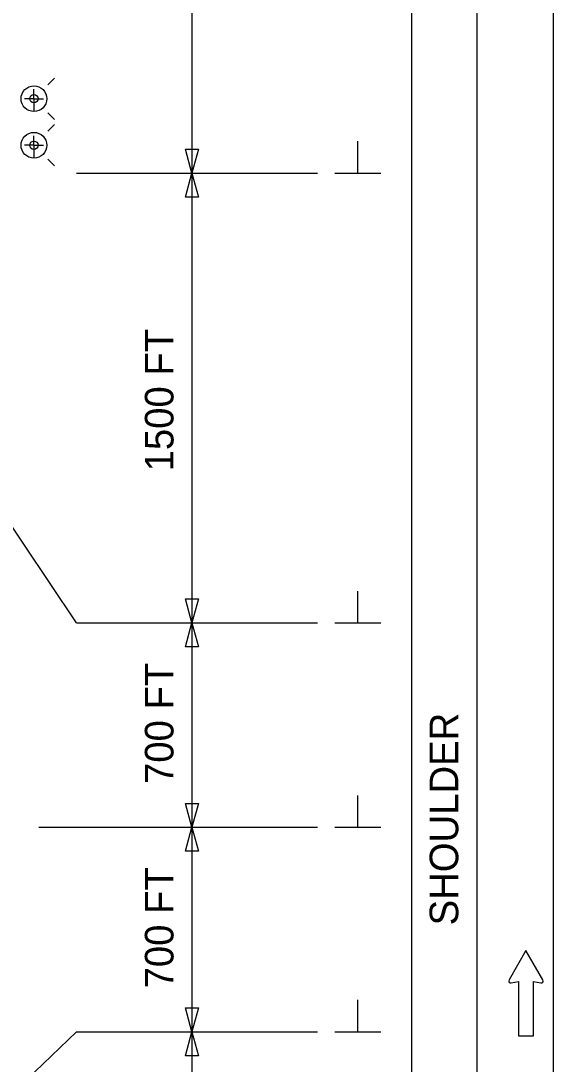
# Model space of a CAD drawing. Extents: x 15273 to 18137, y 1908 to 6555.
# Drawn here: x 16480.8 to 16611, y 2540.6 to 2795.7 of the extents above; entities that cross this region are included whole.
import ezdxf

# ---------------------------------------------------------------- set-up
doc = ezdxf.new("R2010")
doc.units = 0
for name, color, linetype in [('ALI_LEGAL_EX', 7, 'Continuous'), ('MT_SCRATCH_LEVEL_E', 7, 'Continuous'), ('PAVT_EDGE_EX', 7, 'Continuous'), ('TRAFFIC_SIGNS_PR', 7, 'Continuous'), ('TYPICAL_TEXT_DIMEN_PR', 7, 'Continuous')]:
    doc.layers.add(name, color=color, linetype=linetype)

msp = doc.modelspace()

# ---------------------------------------------------------------- linework, layer by layer
at = {"layer": 'ALI_LEGAL_EX'}
msp.add_line((16610.98, 3236.46), (16610.98, 2407.28), dxfattribs=at)
at = {"layer": 'MT_SCRATCH_LEVEL_E'}
for p, q in [((16604.32, 2568.38), (16600.21, 2561.14)), ((16608.47, 2561.14), (16604.32, 2568.38)), ((16600.69, 2560.45), (16602.47, 2560.77)), ((16602.47, 2560.77), (16602.47, 2547.51)), ((16606.21, 2547.51), (16606.21, 2560.77)), ((16606.21, 2560.77), (16607.99, 2560.45)), ((16602.47, 2547.51), (16606.21, 2547.51))]:
    msp.add_line(p, q, dxfattribs=at)
for centre, start, end in [((16600.62, 2560.91), 150.4248, 279.9638), ((16608.06, 2560.91), 260.0362, 29.7731)]:
    msp.add_arc(centre, 0.463, start, end, dxfattribs=at)
at = {"layer": 'PAVT_EDGE_EX'}
for p, q in [((16576.35, 3138.78), (16576.35, 2305.55)), ((16592.35, 3138.78), (16592.35, 2305.55))]:
    msp.add_line(p, q, dxfattribs=at)
at = {"layer": 'TRAFFIC_SIGNS_PR'}
for p, q in [((16487.39, 2780.1), (16489.02, 2781.72)), ((16483.96, 2776.67), (16483.96, 2778.97)), ((16483.96, 2776.67), (16481.66, 2776.67)), ((16483.96, 2776.67), (16483.96, 2773.52)), ((16483.96, 2776.67), (16486.27, 2776.67)), ((16489.01, 2771.62), (16487.39, 2773.25)), ((16487.39, 2768.7), (16489.02, 2770.33)), ((16483.96, 2765.28), (16483.96, 2767.58)), ((16483.96, 2765.28), (16481.66, 2765.28)), ((16483.96, 2765.28), (16483.96, 2762.13)), ((16483.96, 2765.28), (16486.27, 2765.28)), ((16489.01, 2760.23), (16487.39, 2761.86))]:
    msp.add_line(p, q, dxfattribs=at)
for centre, radius in [((16483.96, 2776.67), 3.15), ((16483.96, 2776.67), 1.02), ((16483.96, 2765.28), 3.15), ((16483.96, 2765.28), 1.02)]:
    msp.add_circle(centre, radius, dxfattribs=at)
at = {"layer": 'TYPICAL_TEXT_DIMEN_PR'}
for p, q in [((16522.62, 2868.48), (16522.62, 2758.48)), ((16563.23, 2758.48), (16563.23, 2766.26)), ((16522.62, 2758.48), (16521.06, 2764.34)), ((16521.06, 2764.34), (16522.62, 2764.34)), ((16522.62, 2764.34), (16524.19, 2764.34)), ((16524.19, 2764.34), (16522.62, 2758.48)), ((16494.38, 2758.48), (16553.35, 2758.48)), ((16521.06, 2752.61), (16522.62, 2758.48)), ((16521.06, 2752.61), (16522.62, 2758.48)), ((16522.62, 2758.48), (16522.62, 2648.48)), ((16522.62, 2758.48), (16524.19, 2752.61)), ((16522.62, 2758.48), (16524.19, 2752.61)), ((16557.6, 2758.48), (16568.85, 2758.48)), ((16522.62, 2752.61), (16521.06, 2752.61)), ((16522.62, 2752.61), (16521.06, 2752.61)), ((16524.19, 2752.61), (16522.62, 2752.61)), ((16524.19, 2752.61), (16522.62, 2752.61)), ((16494.38, 2648.48), (16459.72, 2700.07)), ((16563.23, 2648.48), (16563.23, 2656.26)), ((16522.62, 2648.48), (16521.06, 2654.34)), ((16521.06, 2654.34), (16522.62, 2654.34)), ((16522.62, 2648.48), (16521.06, 2654.34)), ((16521.06, 2654.34), (16522.62, 2654.34)), ((16522.62, 2654.34), (16524.19, 2654.34)), ((16524.19, 2654.34), (16522.62, 2648.48)), ((16522.62, 2654.34), (16524.19, 2654.34)), ((16524.19, 2654.34), (16522.62, 2648.48)), ((16494.38, 2648.48), (16553.35, 2648.48)), ((16521.05, 2642.61), (16522.62, 2648.48)), ((16522.62, 2648.48), (16522.62, 2598.48)), ((16522.62, 2648.48), (16524.2, 2642.61)), ((16557.6, 2648.48), (16568.85, 2648.48)), ((16522.62, 2642.61), (16521.05, 2642.61)), ((16524.2, 2642.61), (16522.62, 2642.61)), ((16563.23, 2598.48), (16563.23, 2606.26)), ((16522.62, 2598.48), (16521.05, 2604.34)), ((16521.05, 2604.34), (16522.62, 2604.34)), ((16522.62, 2604.34), (16524.2, 2604.34)), ((16524.2, 2604.34), (16522.62, 2598.48)), ((16485.14, 2598.48), (16553.35, 2598.48)), ((16521.05, 2592.61), (16522.62, 2598.48)), ((16522.62, 2598.48), (16522.62, 2548.48)), ((16522.62, 2598.48), (16524.2, 2592.61)), ((16557.6, 2598.48), (16568.85, 2598.48)), ((16522.62, 2592.61), (16521.05, 2592.61)), ((16524.2, 2592.61), (16522.62, 2592.61)), ((16522.62, 2548.48), (16521.05, 2554.34)), ((16521.05, 2554.34), (16522.62, 2554.34)), ((16522.62, 2554.34), (16524.2, 2554.34)), ((16524.2, 2554.34), (16522.62, 2548.48)), ((16563.23, 2548.48), (16563.23, 2556.26)), ((16494.38, 2548.48), (16432.89, 2489.71)), ((16494.38, 2548.48), (16553.35, 2548.48)), ((16521.05, 2542.61), (16522.62, 2548.48)), ((16522.62, 2548.48), (16522.62, 2498.48)), ((16522.62, 2548.48), (16524.2, 2542.61)), ((16557.6, 2548.48), (16568.85, 2548.48)), ((16522.62, 2542.61), (16521.05, 2542.61)), ((16524.2, 2542.61), (16522.62, 2542.61))]:
    msp.add_line(p, q, dxfattribs=at)

# ---------------------------------------------------------------- texts
for s, p in [('1500 FT', (16518.1, 2685.52)), ('700 FT', (16518.1, 2609.07)), ('SHOULDER', (16587.77, 2574.49)), ('700 FT', (16518.1, 2559.07))]:
    msp.add_text(s, height=7, rotation=90, dxfattribs=at).set_placement(p)

doc.saveas('drawing.dxf')
